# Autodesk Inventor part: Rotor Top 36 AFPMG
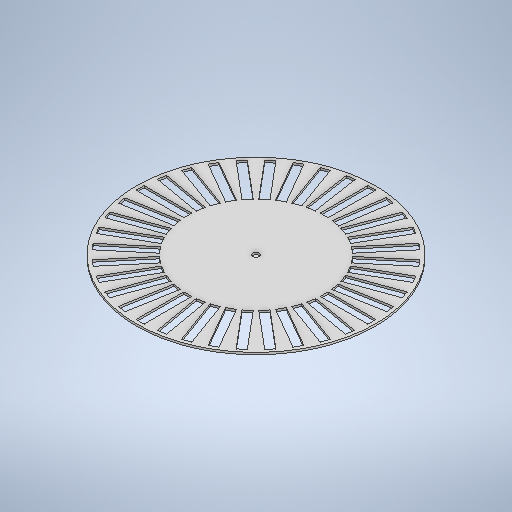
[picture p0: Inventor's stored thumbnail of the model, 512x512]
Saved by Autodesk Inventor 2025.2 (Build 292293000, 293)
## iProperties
Created: 2025-05
Part Number: Rotor Top 36 AFPMG
Material: Generic
Document SubType Name: Modeling
Designer: bensa
Density: 1 g/cm^3
Appearance: Default
Author: bensa
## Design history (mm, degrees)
sketch "Sketch1"
  geometry: C1 r 150 at (0, 0); 1 further point
  constraints: 1 centre point, 1 coincident
  dimensions: "d0" = 300 diameter of C1
extrude "Extrusion1" new body sketch "Sketch1" distance "d1" = 2.6; taper "d2" = 0 deg
sketch "Sketch2"
  geometry: L1 (0, -115.5)-(0, 115.5); L2 (-85.069, 9.923)-(-144.158, 20.342); L3 (-144.158, 20.342)-(-142.421, 30.19); L4 (-142.421, 30.19)-(-83.333, 19.771); L5 (-83.333, 19.771)-(-85.069, 9.923); L6 (-85.069, 9.923)-(-142.421, 30.19); L7 (-144.158, 20.342)-(-83.333, 19.771); L8 (-82.054, 24.544)-(-138.435, 45.065); L9 (-138.435, 45.065)-(-135.015, 54.462); L10 (-135.015, 54.462)-(-78.634, 33.941); L11 (-78.634, 33.941)-(-82.054, 24.544); L12 (-82.054, 24.544)-(-135.015, 54.462); L13 (-138.435, 45.065)-(-78.634, 33.941); L14 (-71.545, 47.08)-(-123.507, 77.08); L15 (-123.507, 77.08)-(-128.507, 68.42); L16 (-128.507, 68.42)-(-76.545, 38.42); L17 (-76.545, 38.42)-(-71.545, 47.08); L18 (-71.545, 47.08)-(-128.507, 68.42); L19 (-123.507, 77.08)-(-76.545, 38.42); L20 (-62.283, 58.789)-(-108.246, 97.356); L21 (-108.246, 97.356)-(-114.673, 89.695); L22 (-114.673, 89.695)-(-68.711, 51.128); L23 (-68.711, 51.128)-(-62.283, 58.789); L24 (-62.283, 58.789)-(-114.673, 89.695); L25 (-108.246, 97.356)-(-68.711, 51.128); L26 (-51.128, 68.711)-(-89.695, 114.673); L27 (-89.695, 114.673)-(-97.356, 108.246); L28 (-97.356, 108.246)-(-58.789, 62.283); L29 (-58.789, 62.283)-(-51.128, 68.711); L30 (-51.128, 68.711)-(-97.356, 108.246); L31 (-89.695, 114.673)-(-58.789, 62.283); L32 (-38.42, 76.545)-(-68.42, 128.507); L33 (-68.42, 128.507)-(-77.08, 123.507); L34 (-77.08, 123.507)-(-47.08, 71.545); L35 (-47.08, 71.545)-(-38.42, 76.545); L36 (-38.42, 76.545)-(-77.08, 123.507); L37 (-68.42, 128.507)-(-47.08, 71.545); L38 (-24.544, 82.054)-(-45.065, 138.435); L39 (-45.065, 138.435)-(-54.462, 135.015); L40 (-54.462, 135.015)-(-33.941, 78.634); L41 (-33.941, 78.634)-(-24.544, 82.054); L42 (-24.544, 82.054)-(-54.462, 135.015); L43 (-45.065, 138.435)-(-33.941, 78.634); L44 (-10.625, 84.831)-(-19.601, 144.156); L45 (-19.601, 144.156)-(-29.488, 142.66); L46 (-29.488, 142.66)-(-20.512, 83.335); L47 (-20.512, 83.335)-(-10.625, 84.831); L48 (-10.625, 84.831)-(-29.488, 142.66); L49 (-19.601, 144.156)-(-20.512, 83.335); L50 (5, 85.5)-(5, 145.5); L51 (5, 145.5)-(-5, 145.5); L52 (-5, 145.5)-(-5, 85.5); L53 (-5, 85.5)-(5, 85.5); L54 (5, 85.5)-(-5, 145.5); L55 (5, 145.5)-(-5, 85.5); L56 (10.625, 84.831)-(19.601, 144.156); L57 (19.601, 144.156)-(29.488, 142.66); L58 (29.488, 142.66)-(20.512, 83.335); L59 (20.512, 83.335)-(10.625, 84.831); L60 (10.625, 84.831)-(29.488, 142.66); L61 (19.601, 144.156)-(20.512, 83.335); L62 (33.628, 78.694)-(54.739, 134.857); L63 (54.739, 134.857)-(45.378, 138.375); L64 (45.378, 138.375)-(24.268, 82.212)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; 2 further points
  constraints: 442 end point, 73 parallel, 36 perpendicular, 5 horizontal, 5 midpoint, 4 equal length, 2 vertical
  dimensions: "d31" = 60 distance of L2.start L2.end; "d32" = 10 distance of L2.end L3.end; "d33" = 60 distance of L8.start L8.end; "d34" = 10 distance of L8.end L9.end; "d35" = 60 distance of L14.start L14.end; "d36" = 10 distance of L15.end L14.end; "d37" = 60 distance of L20.start L20.end; "d38" = 10 distance of L21.end L20.end; "d39" = 60 distance of L26.start L26.end; "d40" = 10 distance of L27.end L26.end; "d41" = 60 distance of L32.start L32.end; "d42" = 10 distance of L33.end L32.end; "d43" = 60 distance of L38.start L38.end; "d44" = 10 distance of L39.end L38.end; "d45" = 60 distance of L44.start L44.end; "d46" = 10 distance of L45.end L44.end; "d47" = 60 distance of L50.start L50.end; "d48" = 10 distance of L51.end L50.end; "d49" = 60 distance of L56.start L56.end; "d50" = 10 distance of L56.end L57.end; "d51" = 60 distance of L62.start L62.end; "d52" = 10 distance of L63.end L62.end; "d53" = 60 distance of L68.start L68.end; "d54" = 10 distance of L69.end L68.end; "d55" = 60 distance of L74.start L74.end; "d56" = 10 distance of L75.end L74.end; "d57" = 60 distance of L80.start L80.end; "d58" = 40 deg angle of L86 L80; "d59" = 10 distance of L80.end L81.end; "d60" = 60 distance of L87.start L87.end; "d61" = 30 deg angle of L93 L87; "d62" = 10 distance of L88.end L87.end; "d63" = 60 distance of L94.start L94.end; "d64" = 20 deg angle of L100 L94; "d65" = 10 distance of L95.end L94.end; "d66" = 60 distance of L101.start L101.end; "d67" = 10 deg angle of L107 L101; "d68" = 10 distance of L102.end L101.end; "d69" = 60 distance of L108.start L108.end; "d70" = 10 distance of L109.end L108.end; "d71" = 60 distance of L114.start L114.end; "d72" = 10 distance of L114.end L115.end; "d73" = 60 distance of L120.start L120.end; "d74" = 10 distance of L120.end L121.end; "d75" = 60 distance of L126.start L126.end; "d76" = 10 distance of L127.end L126.end; "d77" = 60 distance of L132.start L132.end; "d78" = 10 distance of L132.end L133.end; "d79" = 60 distance of L138.start L138.end; "d80" = 10 distance of L138.end L139.end; "d81" = 60 distance of L144.start L144.end; "d82" = 10 distance of L144.end L145.end; "d83" = 60 distance of L150.start L150.end; "d84" = 10 distance of L150.end L151.end; "d85" = 60 distance of L156.start L156.end; "d86" = 10 distance of L157.end L156.end; "d87" = 60 distance of L162.start L162.end; "d88" = 10 distance of L163.end L162.end; "d89" = 60 distance of L168.start L168.end; "d90" = 10 distance of L169.end L168.end; "d91" = 60 distance of L174.start L174.end; "d92" = 10 distance of L175.end L174.end; "d93" = 60 distance of L180.start L180.end; "d94" = 10 distance of L181.end L180.end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
extrude "Extrusion2" cut sketch "Sketch2" distance "d107" = 2.6; taper "d108" = 0 deg
sketch "Sketch3"
  geometry: C1 r 4 at (0, 0); 1 further point
  constraints: 1 centre point, 1 coincident
  dimensions: "d109" = 8 diameter of C1
extrude "Extrusion3" cut sketch "Sketch3" distance "d110" = 2.6; taper "d111" = 0 deg
body "Solid1"
